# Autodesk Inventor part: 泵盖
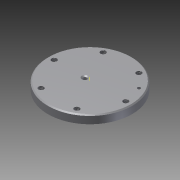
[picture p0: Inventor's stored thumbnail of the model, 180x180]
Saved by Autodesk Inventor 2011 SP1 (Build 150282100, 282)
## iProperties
Created: 2013-12
Part Number: 泵盖
Document SubType Name: Modeling
Designer: Administrator
Density: 1 g/cm^3
Author: Administrator
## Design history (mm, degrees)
sketch "草图1"
  geometry: C1 r 41 at (0, 0); 1 further point
  constraints: 1 centre point, 1 coincident
  dimensions: "d0" = 82 diameter of C1
extrude "拉伸1" new body sketch "草图1" distance "d1" = 8; taper "d2" = 0 deg
sketch "草图2"
  geometry: C1 r 41 at (0, 0) reference; C2 r 24 at (0, 0)
  constraints: 1 centre point, 1 coincident
  dimensions: "d3" = 48 diameter of C2
extrude "拉伸2" join sketch "草图2" distance "d4" = 2; taper "d5" = 0 deg
sketch "草图3"
  geometry: C1 r 41 at (0, 0) reference; 1 further point
  dimensions: "d6" = 35 distance of C1.centre point (-35, 0)
hole "Hole1" sketch "草图3" at (-35, 0) diameter "d7" = 4.917; stored, may be unused: countersink angle "d11" = 90 deg, drill point angle "d13" = 118 deg; dims "d8" = 6, "d9" = 4, "d10" = 2, "d12" = 8
pattern_circular "环形阵列1" dims angle "d15" = 360 deg
chamfer "倒角1" distance "d17" = 1; stored, may be unused: second distance "d18" = 2, angle "d19" = 45 deg
sketch "草图4"
  geometry: C1 r 40 at (0, 0) reference; 1 further point
  dimensions: "d20" = 5 distance of C1.centre point (-5, 0)
hole "Hole2" sketch "草图4" at (-5, 0) diameter "d21" = 4; stored, may be unused: countersink angle "d25" = 90 deg, drill point angle "d27" = 118 deg; dims "d22" = 6, "d23" = 6, "d24" = 2, "d26" = 8
sketch "草图5"
  geometry: 1 further point
hole "Hole3" sketch "草图5" at (30.311, 17.5) diameter "d29" = 3; stored, may be unused: countersink angle "d33" = 90 deg, drill point angle "d35" = 118 deg; dims "d30" = 6, "d31" = 6, "d32" = 2, "d34" = 8
node "实体1"
node "工作轴1"
node "工作轴2"
node "工作轴3"
node "工作轴4"
node "工作轴5"
